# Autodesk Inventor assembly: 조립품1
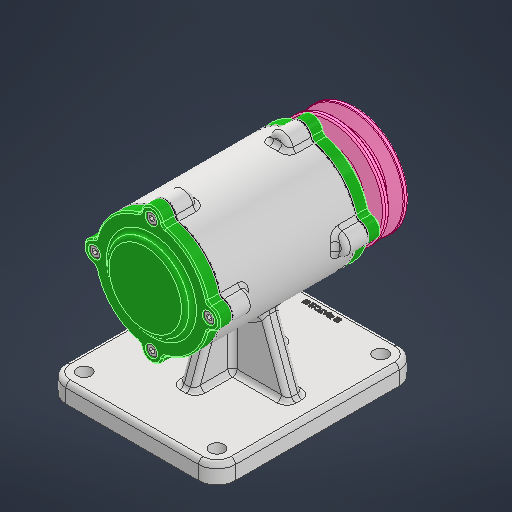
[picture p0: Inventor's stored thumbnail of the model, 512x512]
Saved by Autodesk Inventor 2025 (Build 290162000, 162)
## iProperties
Created: 2025-08
Part Number: 조립품1
Document SubType Name: Assembly
Designer: infra023
Author: infra023
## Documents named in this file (12)
- C:\Users\infra023\Desktop\750806V1009\조립품1.iam
- C:\Users\infra023\Desktop\750806V1009\본체.ipt
- C:\Users\infra023\Desktop\750806V1009\V-벨트풀리\V-벨트풀리.ipt
- C:\Users\infra023\Desktop\750806V1009\개스킷\개스킷.ipt
- C:\Users\infra023\Desktop\750806V1009\너트 M12 x 1.25\너트 M12 x 1.25.ipt
- C:\Users\infra023\Desktop\750806V1009\뒤커버\뒤커버.ipt
- C:\Users\infra023\Desktop\750806V1009\베어링 6204\베어링 6204.ipt
- C:\Users\infra023\Desktop\750806V1009\볼트 M4 x 12\볼트 M4 x 12.ipt
- C:\Users\infra023\Desktop\750806V1009\앞커버\앞커버.ipt
- C:\Users\infra023\Desktop\750806V1009\오일 실\오일 실.ipt
- C:\Users\infra023\Desktop\750806V1009\축\축.ipt
- C:\Users\infra023\Desktop\750806V1009\키 4 x 4\키 4 x 4.ipt
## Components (3 placed, 2 different names)
1. V-벨트풀리:1
2. 개스킷:1
3. 개스킷:2
